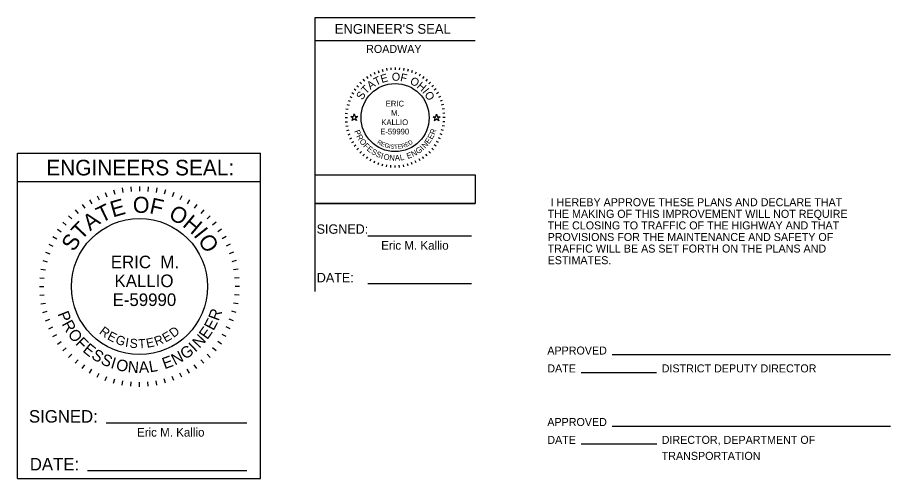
# Model space of a CAD drawing. Extents: x -17.5 to 72.9, y -57.8 to 32.3.
# Drawn here: x 1.19 to 16.45, y -12.1 to -4.04 of the extents above; entities that cross this region are included whole.
import ezdxf

# ---------------------------------------------------------------- set-up
doc = ezdxf.new("R2010")
doc.units = 0
doc.layers.add('SH_Data', color=7, linetype='Continuous')
doc.layers.add('SH_Text', color=7, linetype='Continuous')

msp = doc.modelspace()

# ---------------------------------------------------------------- linework, layer by layer
at = {"layer": 'SH_Data'}
for p, q in [((6.393, -8.836), (6.393, -4.044)), ((6.393, -4.044), (9.193, -4.044)), ((6.393, -4.444), (9.193, -4.444)), ((7.356, -5.036), (7.376, -5.071)), ((7.424, -5.001), (7.44, -5.037)), ((7.494, -4.972), (7.508, -5.01)), ((7.567, -4.949), (7.577, -4.988)), ((7.641, -4.933), (7.648, -4.972)), ((7.717, -4.923), (7.721, -4.962)), ((7.793, -4.919), (7.793, -4.959)), ((7.87, -4.923), (7.866, -4.962)), ((7.945, -4.933), (7.938, -4.972)), ((8.02, -4.949), (8.009, -4.988)), ((8.093, -4.972), (8.079, -5.01)), ((8.163, -5.001), (8.146, -5.037)), ((8.231, -5.036), (8.211, -5.071)), ((7.175, -5.176), (7.203, -5.204)), ((7.231, -5.124), (7.257, -5.155)), ((7.291, -5.077), (7.314, -5.11)), ((8.295, -5.077), (8.272, -5.11)), ((8.356, -5.124), (8.33, -5.155)), ((8.412, -5.176), (8.384, -5.204)), ((7.077, -5.292), (7.109, -5.315)), ((7.123, -5.232), (7.154, -5.258)), ((8.464, -5.232), (8.433, -5.258)), ((8.51, -5.292), (8.477, -5.315)), ((7, -5.424), (7.037, -5.441)), ((7.036, -5.357), (7.07, -5.377)), ((8.551, -5.357), (8.516, -5.377)), ((8.586, -5.424), (8.55, -5.441)), ((6.932, -5.642), (6.971, -5.649)), ((6.948, -5.568), (6.987, -5.578)), ((6.971, -5.495), (7.009, -5.509)), ((8.616, -5.495), (8.578, -5.509)), ((8.639, -5.568), (8.6, -5.578)), ((8.655, -5.642), (8.616, -5.649)), ((6.918, -5.794), (6.958, -5.794)), ((6.922, -5.718), (6.962, -5.721)), ((8.665, -5.718), (8.625, -5.721)), ((8.668, -5.794), (8.628, -5.794)), ((6.922, -5.87), (6.962, -5.867)), ((6.932, -5.946), (6.971, -5.939)), ((8.655, -5.946), (8.616, -5.939)), ((8.665, -5.87), (8.625, -5.867)), ((6.948, -6.021), (6.987, -6.01)), ((6.971, -6.094), (7.009, -6.08)), ((8.616, -6.094), (8.578, -6.08)), ((8.639, -6.021), (8.6, -6.01)), ((7, -6.164), (7.037, -6.147)), ((7.036, -6.232), (7.07, -6.212)), ((8.551, -6.232), (8.516, -6.212)), ((8.586, -6.164), (8.55, -6.147)), ((7.077, -6.296), (7.109, -6.273)), ((7.123, -6.357), (7.154, -6.331)), ((7.175, -6.413), (7.203, -6.385)), ((8.412, -6.413), (8.384, -6.385)), ((8.464, -6.357), (8.433, -6.331)), ((8.51, -6.296), (8.477, -6.273)), ((1.191, -12.102), (1.191, -6.414)), ((1.191, -6.414), (5.441, -6.414)), ((5.441, -12.102), (5.441, -6.414)), ((7.231, -6.465), (7.257, -6.434)), ((7.291, -6.511), (7.314, -6.478)), ((7.356, -6.552), (7.376, -6.517)), ((7.424, -6.587), (7.44, -6.551)), ((8.163, -6.587), (8.146, -6.551)), ((8.231, -6.552), (8.211, -6.517)), ((8.295, -6.511), (8.272, -6.478)), ((8.356, -6.465), (8.33, -6.434)), ((7.494, -6.616), (7.508, -6.579)), ((7.567, -6.639), (7.577, -6.601)), ((7.641, -6.656), (7.648, -6.617)), ((7.717, -6.666), (7.721, -6.626)), ((7.793, -6.669), (7.793, -6.629)), ((7.87, -6.666), (7.866, -6.626)), ((7.945, -6.656), (7.938, -6.617)), ((8.02, -6.639), (8.009, -6.601)), ((8.093, -6.616), (8.079, -6.579)), ((1.191, -6.908), (5.441, -6.908)), ((3.171, -7.004), (3.178, -7.083)), ((3.324, -6.997), (3.324, -7.077)), ((3.476, -7.004), (3.469, -7.083)), ((2.584, -7.161), (2.618, -7.233)), ((2.725, -7.102), (2.753, -7.178)), ((2.871, -7.057), (2.891, -7.134)), ((3.02, -7.023), (3.034, -7.102)), ((3.628, -7.023), (3.614, -7.102)), ((3.777, -7.057), (3.756, -7.134)), ((3.922, -7.102), (3.895, -7.178)), ((4.063, -7.161), (4.029, -7.233)), ((2.32, -7.313), (2.366, -7.379)), ((2.449, -7.231), (2.489, -7.301)), ((4.199, -7.231), (4.159, -7.301)), ((4.327, -7.313), (4.282, -7.379)), ((5.441, -12.102), (5.441, -7.31)), ((6.393, -7.294), (9.193, -7.294)), ((10.46, -7.203), (10.46, -7.203)), ((2.199, -7.406), (2.25, -7.468)), ((4.449, -7.406), (4.397, -7.468)), ((1.983, -7.622), (2.044, -7.673)), ((2.086, -7.509), (2.143, -7.566)), ((4.561, -7.509), (4.505, -7.566)), ((4.664, -7.622), (4.603, -7.673)), ((1.89, -7.743), (1.956, -7.789)), ((4.757, -7.743), (4.692, -7.789)), ((1.808, -7.872), (1.877, -7.912)), ((4.839, -7.872), (4.77, -7.912)), ((7.316, -7.86), (9.128, -7.86)), ((1.738, -8.007), (1.81, -8.041)), ((4.91, -8.007), (4.837, -8.041)), ((1.679, -8.148), (1.754, -8.176)), ((4.968, -8.148), (4.893, -8.176)), ((1.633, -8.294), (1.711, -8.315)), ((5.014, -8.294), (4.937, -8.315)), ((1.6, -8.443), (1.679, -8.457)), ((5.047, -8.443), (4.968, -8.457)), ((1.58, -8.594), (1.66, -8.601)), ((5.067, -8.594), (4.987, -8.601)), ((7.316, -8.695), (9.128, -8.695)), ((1.574, -8.747), (1.654, -8.747)), ((5.074, -8.747), (4.994, -8.747)), ((1.58, -8.899), (1.66, -8.892)), ((5.067, -8.899), (4.987, -8.892)), ((1.6, -9.051), (1.679, -9.037)), ((5.047, -9.051), (4.968, -9.037)), ((1.633, -9.2), (1.711, -9.179)), ((5.014, -9.2), (4.937, -9.179)), ((1.679, -9.345), (1.754, -9.318)), ((1.738, -9.486), (1.81, -9.453)), ((4.91, -9.486), (4.837, -9.453)), ((4.968, -9.345), (4.893, -9.318)), ((1.808, -9.622), (1.877, -9.582)), ((4.839, -9.622), (4.77, -9.582)), ((1.89, -9.751), (1.956, -9.705)), ((4.757, -9.751), (4.692, -9.705)), ((1.983, -9.872), (2.044, -9.82)), ((4.664, -9.872), (4.603, -9.82)), ((2.086, -9.984), (2.143, -9.928)), ((2.199, -10.087), (2.25, -10.026)), ((4.449, -10.087), (4.397, -10.026)), ((4.561, -9.984), (4.505, -9.928)), ((11.589, -9.935), (16.454, -9.935)), ((2.32, -10.18), (2.366, -10.115)), ((2.449, -10.262), (2.489, -10.193)), ((4.199, -10.262), (4.159, -10.193)), ((4.327, -10.18), (4.282, -10.115)), ((2.584, -10.333), (2.618, -10.26)), ((2.725, -10.391), (2.753, -10.316)), ((2.871, -10.437), (2.891, -10.36)), ((3.777, -10.437), (3.756, -10.36)), ((3.922, -10.391), (3.895, -10.316)), ((4.063, -10.333), (4.029, -10.26)), ((11.045, -10.247), (12.362, -10.247)), ((3.02, -10.47), (3.034, -10.392)), ((3.171, -10.49), (3.178, -10.411)), ((3.324, -10.497), (3.324, -10.417)), ((3.476, -10.49), (3.469, -10.411)), ((3.628, -10.47), (3.614, -10.392)), ((2.743, -11.126), (5.199, -11.126)), ((11.589, -11.184), (16.454, -11.184)), ((11.045, -11.496), (12.368, -11.496)), ((2.416, -11.961), (5.199, -11.961)), ((1.191, -12.102), (5.441, -12.102))]:
    msp.add_line(p, q, dxfattribs=at)
for points in [[(7.017, -5.774), (7.064, -5.774), (7.078, -5.73), (7.093, -5.774), (7.14, -5.774), (7.102, -5.802), (7.116, -5.846), (7.078, -5.819), (7.04, -5.846), (7.055, -5.802)], [(8.456, -5.78), (8.503, -5.78), (8.517, -5.735), (8.532, -5.78), (8.579, -5.78), (8.541, -5.807), (8.555, -5.852), (8.517, -5.824), (8.479, -5.852), (8.494, -5.807)], [(6.393, -7.294), (6.393, -6.794), (9.193, -6.794), (9.193, -7.294)]]:
    msp.add_lwpolyline(points, close=True, dxfattribs=at)
for centre, radius in [((7.793, -5.794), 0.595), ((3.324, -8.747), 1.19)]:
    msp.add_circle(centre, radius, dxfattribs=at)

# ---------------------------------------------------------------- texts
for s, height, p in [("ENGINEER'S SEAL", 0.17, (6.738, -4.329)), ('ROADWAY', 0.14, (7.287, -4.664)), ('ERIC', 0.1, (7.629, -5.6)), ('M.', 0.1, (7.722, -5.763)), ('KALLIO', 0.1, (7.552, -5.925)), ('E-59990', 0.1, (7.533, -6.088)), ('ENGINEERS SEAL:', 0.273, (1.694, -6.805)), (' I HEREBY APPROVE THESE PLANS AND DECLARE THAT', 0.14, (10.46, -7.343)), ('THE MAKING OF THIS IMPROVEMENT WILL NOT REQUIRE', 0.14, (10.46, -7.546)), ('THE CLOSING TO TRAFFIC OF THE HIGHWAY AND THAT', 0.14, (10.46, -7.748)), ('SIGNED:', 0.1641, (6.421, -7.824)), ('PROVISIONS FOR THE MAINTENANCE AND SAFETY OF', 0.14, (10.46, -7.951)), ('Eric M. Kallio', 0.15118, (7.55, -8.103)), ('TRAFFIC WILL BE AS SET FORTH ON THE PLANS AND', 0.14, (10.46, -8.153)), ('ERIC  M.', 0.22, (2.823, -8.427)), ('ESTIMATES.', 0.14, (10.46, -8.356)), ('KALLIO', 0.22, (2.888, -8.757)), ('DATE:', 0.1641, (6.424, -8.672)), ('E-59990', 0.22, (2.854, -9.087)), ('SIGNED:', 0.2188, (1.392, -11.125)), ('Eric M. Kallio', 0.15118, (3.281, -11.369)), ('DATE:', 0.2188, (1.407, -11.96))]:
    msp.add_text(s, height=height, dxfattribs=at).set_placement(p)
for s, height, rotation, p in [('E', 0.14, 15.7571, (7.56, -5.191)), ('O', 0.14, 359.7812, (7.735, -5.15)), ('F', 0.14, 347.4362, (7.874, -5.153)), ('A', 0.14, 36.4747, (7.362, -5.312)), ('T', 0.14, 25.7167, (7.459, -5.24)), ('O', 0.14, 332.2586, (8.04, -5.196)), ('H', 0.14, 319.9136, (8.162, -5.263)), ('S', 0.14, 57.1924, (7.219, -5.496)), ('T', 0.14, 46.4344, (7.285, -5.394)), ('I', 0.14, 308.367, (8.261, -5.347)), ('O', 0.14, 303.1491, (8.299, -5.391)), ('P', 0.1, 291.494, (7.076, -6.032)), ('R', 0.1, 298.7311, (7.111, -6.121)), ('E', 0.1, 61.9951, (8.441, -6.185)), ('R', 0.1, 69.2322, (8.485, -6.101)), ('O', 0.1, 306.4666, (7.162, -6.21)), ('F', 0.1, 314.7068, (7.228, -6.296)), ('R', 0.075, 327.8239, (7.473, -6.24)), ('E', 0.075, 337.7777, (7.537, -6.281)), ('G', 0.075, 344.2727, (7.602, -6.309)), ('E', 0.075, 8.9826, (7.843, -6.341)), ('R', 0.075, 17.6836, (7.912, -6.332)), ('E', 0.075, 23.3052, (7.984, -6.309)), ('D', 0.075, 31.466, (8.048, -6.281)), ('N', 0.1, 47.0224, (8.318, -6.339)), ('E', 0.1, 54.758, (8.386, -6.264)), ('E', 0.1, 321.4393, (7.29, -6.359)), ('S', 0.1, 328.6764, (7.366, -6.418)), ('S', 0.1, 335.9134, (7.447, -6.467)), ('I', 0.075, 350.6464, (7.68, -6.331)), ('S', 0.075, 353.7858, (7.709, -6.336)), ('T', 0.075, 3.0061, (7.778, -6.344)), ('E', 0.1, 20.0742, (8.014, -6.518)), ('N', 0.1, 27.3113, (8.103, -6.484)), ('G', 0.1, 35.0469, (8.193, -6.436)), ('I', 0.1, 43.287, (8.281, -6.372)), ('I', 0.1, 343.1505, (7.535, -6.505)), ('O', 0.1, 346.8859, (7.582, -6.52)), ('N', 0.1, 355.1261, (7.688, -6.543)), ('A', 0.1, 2.8617, (7.79, -6.55)), ('L', 0.1, 10.0987, (7.885, -6.545)), ('T', 0.28, 25.7167, (2.656, -7.639)), ('E', 0.28, 15.7571, (2.858, -7.54)), ('O', 0.28, 359.7812, (3.208, -7.458)), ('F', 0.28, 347.4362, (3.486, -7.463)), ('A', 0.28, 36.4747, (2.461, -7.783)), ('O', 0.28, 332.2586, (3.816, -7.551)), ('T', 0.28, 46.4344, (2.307, -7.947)), ('H', 0.28, 319.9136, (4.061, -7.684)), ('I', 0.28, 308.367, (4.258, -7.853)), ('S', 0.28, 57.1924, (2.176, -8.151)), ('O', 0.28, 303.1491, (4.336, -7.941)), ('R', 0.2, 69.2322, (4.706, -9.36)), ('P', 0.2, 291.494, (1.888, -9.223)), ('E', 0.2, 61.9951, (4.618, -9.529)), ('R', 0.2, 298.7311, (1.96, -9.4)), ('R', 0.16, 323.2378, (2.609, -9.559)), ('D', 0.16, 38.0378, (3.92, -9.649)), ('E', 0.2, 54.758, (4.509, -9.686)), ('O', 0.2, 306.4666, (2.06, -9.578)), ('E', 0.16, 332.4256, (2.748, -9.662)), ('G', 0.16, 341.0076, (2.891, -9.738)), ('R', 0.16, 20.268, (3.616, -9.788)), ('E', 0.16, 29.4558, (3.779, -9.728)), ('N', 0.2, 47.0224, (4.372, -9.837)), ('F', 0.2, 314.7068, (2.192, -9.75)), ('E', 0.2, 321.4393, (2.318, -9.876)), ('I', 0.16, 350.8085, (3.066, -9.797)), ('S', 0.16, 355.1352, (3.146, -9.814)), ('T', 0.16, 3.7172, (3.307, -9.828)), ('E', 0.16, 11.686, (3.457, -9.82)), ('I', 0.2, 43.287, (4.299, -9.903)), ('S', 0.2, 328.6764, (2.468, -9.994)), ('N', 0.2, 27.3113, (3.943, -10.127)), ('G', 0.2, 35.0469, (4.123, -10.031)), ('S', 0.2, 335.9134, (2.632, -10.092)), ('I', 0.2, 343.1505, (2.807, -10.168)), ('O', 0.2, 346.8859, (2.9, -10.199)), ('N', 0.2, 355.1261, (3.113, -10.244)), ('A', 0.2, 2.8617, (3.316, -10.259)), ('L', 0.2, 10.0987, (3.507, -10.248)), ('E', 0.2, 20.0742, (3.764, -10.194))]:
    msp.add_text(s, height=height, rotation=rotation, dxfattribs=at).set_placement(p)
at = {"layer": 'SH_Text'}
for s, p in [('APPROVED', (10.454, -9.935)), ('DATE', (10.454, -10.247)), ('DISTRICT DEPUTY DIRECTOR', (12.454, -10.247)), ('APPROVED', (10.454, -11.184)), ('DATE', (10.454, -11.496)), ('DIRECTOR, DEPARTMENT OF', (12.454, -11.496)), ('TRANSPORTATION', (12.454, -11.776))]:
    msp.add_text(s, height=0.14, dxfattribs=at).set_placement(p)

doc.saveas('drawing.dxf')
